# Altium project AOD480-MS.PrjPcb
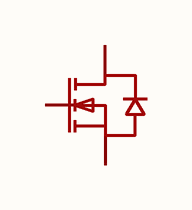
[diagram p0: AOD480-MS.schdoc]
1 sheet, 1 parts. Net scope: global (net labels, ports and power ports of the same name join across sheets).

## Sheet AOD480-MS.schdoc
size 127 x 101 mm

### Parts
Q?  aod480-ms  [TO-252-2_L6.6-W6.1-P4.57-LS10.0-BR-1]  (value not drawn)

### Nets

Not connected (* = marked no-connect by the designer): Q? 1(G) 2(D) 3(S)

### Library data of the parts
Q? = aod480-ms: 数量:1个N沟道;漏源电压(Vdss):30V;连续漏极电流(Id):20A;导通电阻(RDS(on)):18mΩ@10V;耗散功率(Pd):20.8W;阈值电压(Vgs(th)):1.2V;; Manufacturer: MSKSEMI(美森科); AddInBom: yes; ModelId: 4113ec4a058842b08e2585e7304bd9b4; ModelTransform: 401.574,259.842,0,0,0,0,-36.417,0,0; Number: 1个N沟道; Drain to Source Voltage: 30V; Current - Continuous Drain(Id): 20A; Pd - Power Dissipation: 20.8W; Gate Threshold Voltage (Vgs(th)): 1.2V; Gate Charge(Qg): 4.9nC@4.5V; Input Capacitance(Ciss): 416pF; Reverse Transfer Capacitance (Crss@Vds): 51pF; Type: N沟道; Output Capacitance(Coss): 62pF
